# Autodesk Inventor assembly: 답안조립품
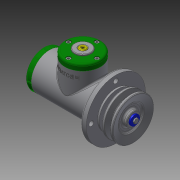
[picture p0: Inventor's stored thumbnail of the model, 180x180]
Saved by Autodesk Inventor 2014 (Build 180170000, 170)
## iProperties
Created: 2016-08
Part Number: 답안조립품
Document SubType Name: Assembly
Designer: USER
Author: USER
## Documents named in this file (25)
- C:\Users\USER\Desktop\460807V1009\답안조립품.iam
- C:\Users\USER\Desktop\460807V1009\본체.ipt
- C:\Users\USER\Desktop\460807V1009\V-벨트풀리.ipt
- C:\Users\USER\Desktop\460807V1009\너트 M10.ipt
- C:\Users\USER\Desktop\460807V1009\링크.ipt
- C:\Users\USER\Desktop\460807V1009\멈춤링 15 x 1.ipt
- C:\Users\USER\Desktop\460807V1009\멈춤링 35x1.6.ipt
- C:\Users\USER\Desktop\460807V1009\베어링 15 x 35 x 11.ipt
- C:\Users\USER\Desktop\460807V1009\볼트 M4 x 10.ipt
- C:\Users\USER\Desktop\460807V1009\볼트 M4 x 12.ipt
- C:\Users\USER\Desktop\460807V1009\부시1.ipt
- C:\Users\USER\Desktop\460807V1009\부시2.ipt
- C:\Users\USER\Desktop\460807V1009\분할핀 1.6 x 12.ipt
- C:\Users\USER\Desktop\460807V1009\사이드 커버.ipt
- 사이드 커버.ipt
- C:\Users\USER\Desktop\460807V1009\슬라이더.ipt
- C:\Users\USER\Desktop\460807V1009\오일 실 15 25 7.ipt
- C:\Users\USER\Desktop\460807V1009\와셔 4x16.ipt
- C:\Users\USER\Desktop\460807V1009\와셔 10x21.ipt
- C:\Users\USER\Desktop\460807V1009\클래스터 핀 6 x 24.ipt
- C:\Users\USER\Desktop\460807V1009\키 4 x 4 x 18.ipt
- C:\Users\USER\Desktop\460807V1009\탑 부시.ipt
- C:\Users\USER\Desktop\460807V1009\탑 커버.ipt
- 탑 커버.ipt
- C:\Users\USER\Desktop\460807V1009\편심축.ipt
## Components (6 placed, 3 different names)
1. V-벨트풀리:1
2. ISO 4017 M4 x 10:1
3. ISO 4762 M4 x 12:1
4. ISO 4762 M4 x 12:2
5. ISO 4762 M4 x 12:3
6. ISO 4762 M4 x 12:4
